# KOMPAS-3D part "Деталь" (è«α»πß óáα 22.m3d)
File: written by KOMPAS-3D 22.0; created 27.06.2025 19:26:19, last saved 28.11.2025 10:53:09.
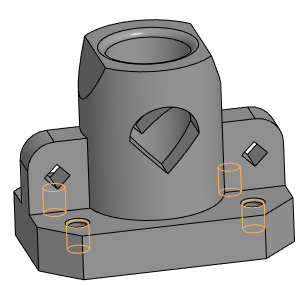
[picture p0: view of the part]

Document properties: Автор: alymovy@yandex.ru; Организация: HP; Полное имя файла: Корпус вар 22.cdw

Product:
- Part/product: Деталь
    Материал: Фторопласт-4 ГОСТ 10007-80 Е (density 2200 kg/m3)
    Масса: 1.155264
    Форматы листов документа: A3

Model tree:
1. Эскиз:1
2. Элемент выдавливания:1
     Расстояние 1 = 25
3. Эскиз:2  (with: Элемент выдавливания:1)
4. Элемент выдавливания:2
     Расстояние 1 = 85
5. Фаска:1  (with: Элемент выдавливания:1)
     Угол = 45; Длина 1 = 20; Длина 2 = 20
6. Эскиз:3  (with: Фаска:1, Элемент выдавливания:2)
7. Ребро жесткости:1
     Толщина стенки 1 = 18; Толщина стенки 2 = 1
8. Зеркальный массив:1
9. Экземпляр ( 1 )
10. Экземпляр ( 2 )  (with: Ребро жесткости:1)
11. Эскиз:4  (with: Элемент выдавливания:2)
12. Элемент выдавливания:3
     Расстояние 2 = 110
13. Эскиз:5  (with: Элемент выдавливания:2)
14. Элемент выдавливания:4
     Расстояние 1 = 47.5
15. Эскиз:6  (with: Ребро жесткости:1)
16. Элемент выдавливания:5
17. Эскиз:7  (with: Элемент выдавливания:3)
18. Элемент выдавливания:6  (with: Элемент выдавливания:3)
     Расстояние 1 = 23; Расстояние 2 = 23
19. Эскиз:8  (with: Элемент выдавливания:1, Элемент выдавливания:2)
20. Отверстие:1  (with: Элемент выдавливания:1, Ребро жесткости:1)  (labels: M12)
     Глубина выреза = 20; Диаметр отверстия = 10.1056; Угол конуса дна = 118; Расстояние 1 = -19; Расстояние 2 = 22; Диаметр зенковки = 13.3056; Глубина зенковки = 1.6; Угол зенковки = 90
21. M12  (labels: cil0_24705-2004 coarse)
     Длина резьбы = 15; Шаг резьбы = 1.75; Номинальный диаметр резьбы = 12
22. Зеркальный массив:2  (with: Экземпляр ( 1 ), Экземпляр ( 2 ), Отверстие:1)
23. Зеркальный массив:3  (with: Экземпляр ( 1 ), Экземпляр ( 2 ), Зеркальный массив:2, Отверстие:1)
24. Экземпляр ( 2 )  (with: Отверстие:1)
25. Скругление:1  (with: Элемент выдавливания:3)  (labels: Фторопласт-4 ГОСТ 10007-80 Е)
     Радиус = 4

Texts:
  Точка начала. Х
  Точка начала. Y
  Точка начала. Z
